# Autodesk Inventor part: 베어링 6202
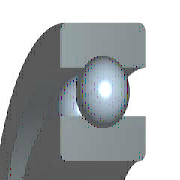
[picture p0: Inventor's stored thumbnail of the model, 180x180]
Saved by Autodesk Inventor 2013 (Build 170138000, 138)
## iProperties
IsCustomPart: 1
Created: 2015-12
Part Number: 베어링 6202
Material: 강철, 연강
Description: 깊은 그루브 볼 베어링
Document SubType Name: Modeling
Standard: KS B 2023
Designer: mdu
Standards Organization: KS
Language: ko-KR
Size Designation: 6202 - 15 x 35 x 11
Categories: <MemberInstance><Categories><Category DisplayName="샤프트 부품" InternalName="7f7aeb1f-a693-4053-b835-cee3144e0d98" Mnemonic="SHFT"><Category DisplayName="베어링" Inter
Density: 7.86 g/cm^3
Mass: 45.8724 g
Surface Area: 51.5584 cm^2
Volume: 5.83618 cm^3
Author: mdu
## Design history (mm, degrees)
sketch "스케치" dims "d0" = 5.2 (= -0.26 x WD + 0.26 x BD)
  geometry: L1 (2.9, 12.5)-(8.1, 12.5); L2 (5.5, 12.5)-(5.5, 9.9); L3 (5.5, 12.5)-(5.5, 15.1); L4 (3.568, 10.76)-(0, 10.76); L5 (0, 7.5)-(11, 7.5); L6 (3.568, 14.24)-(0, 14.24); L7 (0, 17.5)-(11, 17.5); L8 (11, 7.5)-(11, 10.76); L9 (7.432, 10.76)-(11, 10.76); L10 (7.432, 14.24)-(11, 14.24); L11 (11, 17.5)-(11, 14.24); L12 (-1.4, 0)-(8.4, 0) reference; L13 (0, -0.3)-(0, 5.3) reference
  constraints: 22 end point, 4 point on line, 2 collinear, 2 perpendicular, 2 symmetric about line, 1 midpoint, 1 parallel, 14 other
  dimensions: "d9" = 15 diameter of L5 L12 (= WD); "d11" = 35 diameter of L7 L12 (= BD); "d12" = 11 distance between parallel lines of L8 L13 (= KB); "d13" = 21.52 diameter of L9 L12 (= 0.326 x BD + 0.674 x WD)
revolve "본체" stored, may be unused: angle "d6" = 90 deg
revolve "볼" stored, may be unused: angle "d7" = 90 deg
pattern_circular "IDS_ARRAYBALL[SIMPL:T]" dims angle "d3" = 360 deg
body "Solid1"
fillet "모깎기1" dims "d1" = 0.6 (= KRS)
other parameters: "WD" = 15 [user parameter; used in 5 equation terms], "BD" = 35 [user parameter; used in 5 equation terms], "KB" = 11 [user parameter; used in 1 equation term], "KRS" = 0.6 [user parameter; used in 1 equation term], "d4" = 0, "d5" = 0, "d8" = 0, "d14" = 0, "d15" = 0, "BBA" = 0 [user parameter], "BC0" = 3750000 [user parameter], "BC" = 7800000 [user parameter], "BR" = 17.5 (= 0.5 x BD) [user parameter], "WR" = 7.5 (= 0.5 x WD) [user parameter]
